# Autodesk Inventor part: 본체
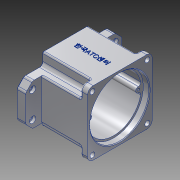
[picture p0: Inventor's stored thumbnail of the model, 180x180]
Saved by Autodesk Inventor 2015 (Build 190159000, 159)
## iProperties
Created: 2016-02
Part Number: 본체
Material: Aluminum 6061
Document SubType Name: Modeling
Designer: Administrator
Density: 2.7 g/cm^3
Appearance: Aluminum - Flat
Mass: 873.805 g
Surface Area: 764.086 cm^2
Volume: 323.632 cm^3
Author: Administrator
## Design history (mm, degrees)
sketch "Sketch1"
  geometry: L1 (60, 30)-(-60, 30); L2 (-70, 20)-(-70, -20); L3 (-60, -30)-(60, -30); L4 (70, -20)-(70, 20); L5 (70, 30)-(-70, -30); L6 (-70, 30)-(70, -30); L7 (60, 30)-(70, 20); L8 (60, -30)-(70, -20); L9 (-60, 30)-(-70, 20); L10 (-60, -30)-(-70, -20); 1 further point
  constraints: 20 end point, 8 point on line, 2 midpoint, 2 parallel, 1 horizontal, 1 perpendicular
  dimensions: "d0" = 140 distance of L6.end L5.end; "d1" = 60 distance of L5.end L6.start; "d2" = 10 distance of L1.start L5.start; "d3" = 10 distance of L4.end L5.start (= d2); "d4" = 10 distance of L3.end L6.end (= d2); "d5" = 10 distance of L4.start L6.end (= d4); "d6" = 10 distance of L1.end L6.start (= d2); "d7" = 10 distance of L2.start L6.start (= d6); "d8" = 10 distance of L3.start L5.end (= d2); "d9" = 10 distance of L2.end L5.end (= d8)
extrude "Extrusion1" new body sketch "Sketch1" distance "d10" = 13; taper "d11" = 0 deg
sketch "Sketch2"
  geometry: L1 (-19, -60)-(19, -60); L2 (19, -60)-(19, 60); L3 (19, 60)-(-19, 60); L4 (-19, 60)-(-19, -60); L5 (-19, -60)-(19, 60); L6 (19, -60)-(-19, 60); 5 further points
  constraints: 12 end point, 4 coincident, 2 midpoint, 2 parallel, 1 horizontal, 1 perpendicular
  dimensions: "d12" = 38 distance of L3.end L2.end; "d13" = 120 distance of L2.end L1.end
hole "Hole1" sketch "Sketch2" at (-19, -60), (19, -60), (19, 60), (-19, 60) diameter "d14" = 5; stored, may be unused: countersink angle "d18" = 90 deg, drill point angle "d20" = 0 deg; dims "d15" = 6.35, "d16" = 9, "d17" = 4, "d19" = 13
sketch "Sketch3"
  geometry: L1 (-47, -47)-(47, -47); L2 (47, -47)-(47, 47); L3 (47, 47)-(-47, 47); L4 (-47, 47)-(-47, -47); L5 (-47, -47)-(47, 47); L6 (47, -47)-(-47, 47); 1 further point
  constraints: 12 end point, 2 midpoint, 2 parallel, 1 horizontal, 1 perpendicular
  dimensions: "d21" = 94 distance of L3.end L2.end; "d22" = 94 distance of L2.end L1.end
extrude "Extrusion2" join sketch "Sketch3" distance "d23" = 67; taper "d24" = 0 deg
sketch "Sketch4"
  geometry: L1 (30, 33)-(47, 33); L2 (47, 33)-(47, 47); L3 (47, 47)-(30, 47); L4 (30, 47)-(30, 33); L5 (30, 33)-(47, 47); L6 (47, 33)-(30, 47); L7 (47, 47)-(47, -47) reference; L8 (30, 47)-(47, 47) reference; 2 further points
  constraints: 12 end point, 2 midpoint, 2 parallel, 1 collinear, 1 horizontal, 1 perpendicular
  dimensions: "d25" = 33 vertical distance of point (0, 0) L1.end; "d26" = 30 distance from line of L4 point (0, 0)
extrude "Extrusion3" cut sketch "Sketch4" distance "d27" = 57; taper "d28" = 0 deg
mirror "Mirror1"
mirror "Mirror2"
sketch "Sketch5"
  geometry: L1 (40, 40)-(-40, 40); L2 (-40, 40)-(-40, -40); L3 (-40, -40)-(40, -40); L4 (40, -40)-(40, 40); L5 (40, 40)-(-40, -40); L6 (-40, 40)-(40, -40); C1 r 3.5 at (-40, -40); C2 r 3.5 at (-40, 40); C3 r 3.5 at (40, 40); C4 r 3.5 at (40, -40); 1 further point
  constraints: 12 end point, 4 centre point, 4 coincident, 2 midpoint, 2 parallel, 1 horizontal, 1 perpendicular
  dimensions: "d29" = 80 distance of L3.end L2.end; "d30" = 80 distance of L2.end L1.end; "d31" = 7 diameter of C1; "d32" = 7 diameter of C2; "d33" = 7 diameter of C3; "d34" = 7 diameter of C4
extrude "Extrusion4" cut sketch "Sketch5" distance "d35" = 10; taper "d36" = 0 deg
sketch "Sketch6"
  geometry: L1 (30, -33)-(47, -33) reference; L2 (47, 33)-(47, -33) reference; L3 (47, 33)-(30, 33) reference; L4 (30, 33)-(30, -33) reference; L5 (-47, -33)-(-30, -33) reference; L6 (-30, -33)-(-30, 33) reference; L7 (-30, 33)-(-47, 33) reference; L8 (-47, -33)-(-47, 33) reference; 1 further point
extrude "Extrusion5" join sketch "Sketch6" distance "d37" = 13; taper "d38" = 0 deg
sketch "Sketch7"
  geometry: C1 r 28 at (11, 0); 1 further point
  constraints: 1 centre point, 1 horizontal alignment
  dimensions: "d39" = 56 diameter of C1; "d40" = 11 distance of point (0, 0) C1.centre
extrude "Extrusion6" join sketch "Sketch7" distance "d41" = 7; taper "d42" = -10 deg
sketch "Sketch8"
  geometry: 2 further points
  constraints: 1 coincident
hole "Hole2" sketch "Sketch8" at (0, 0) diameter "d43" = 80; stored, may be unused: countersink angle "d47" = 90 deg, drill point angle "d49" = 0 deg; dims "d44" = 6.35, "d45" = 86, "d46" = 9, "d48" = 71
sketch "Sketch9"
  geometry: A1 r 21 centre (-11, 0) between (7.984, 8.978) and (7.984, -8.978); A2 r 15 centre (20, 0) between (7.984, -8.978) and (7.984, 8.978); 1 further point
  constraints: 4 point on circle, 2 centre point, 2 horizontal alignment
  dimensions: "d50" = 21 radius of A1; "d51" = 15 radius of A2; "d52" = 11 distance of point (0, 0) A1.centre; "d53" = 20 distance of point (0, 0) A2.centre
extrude "Extrusion7" join sketch "Sketch9" distance "d54" = 7; taper "d55" = 0 deg
hole "Hole3" diameter "d58" = 25; stored, may be unused: countersink angle "d62" = 90 deg, drill point angle "d64" = 0 deg; dims "d59" = 6.35, "d60" = 35, "d61" = 10, "d63" = 15, "d93" = 10, "d94" = 10
hole "Hole4" diameter "d67" = 19; stored, may be unused: countersink angle "d71" = 90 deg, drill point angle "d73" = 0 deg; dims "d65" = 10, "d66" = 10, "d68" = 6.35, "d69" = 22, "d70" = 7, "d72" = 8
hole "Hole5" diameter "d76" = 32; stored, may be unused: countersink angle "d80" = 90 deg, drill point angle "d82" = 0 deg; dims "d77" = 6.35, "d78" = 22, "d79" = 7, "d81" = 8, "d95" = 10, "d96" = 10
chamfer "Chamfer1" distance "d83" = 1; stored, may be unused: second distance "d84" = 2, angle "d85" = 45 deg
fillet "Fillet2" dims "d87" = 2
sketch "Sketch12" dims "d98" = 36
  geometry: A1 r 40 centre (0, 0) between (-8.214, -39.148) and (8.214, -39.148) reference; A2 r 4 centre (0, -36) between (3.997, -35.852) and (-3.997, -35.852); A3 r 3.5 centre (-7.495, -35.722) between (-8.214, -39.148) and (-3.997, -35.852); A4 r 3.5 centre (7.495, -35.722) between (3.997, -35.852) and (8.214, -39.148); A5 r 40 centre (0, 0) between (-8.214, -39.148) and (8.214, -39.148); 2 further points
  constraints: 10 point on circle, 4 centre point, 4 tangent, 2 coincident, 2 vertical alignment, 1 equal radius, 2 other
  dimensions: "d97" = 4 radius of A2; "d99" = 3.5 radius of A3; "d100" = 3.5 radius of A4 (derived)
extrude "Extrusion8" join sketch "Sketch12" distance "d101" = 62; taper "d102" = 0 deg
mirror "Mirror3"
sketch "Sketch13"
  geometry: A1 r 4 centre (0, -36) between (3.997, -35.852) and (-3.997, -35.852) reference; A2 r 4 centre (0, 36) between (-3.997, 35.852) and (3.997, 35.852) reference; 3 further points
  constraints: 2 coincident
hole "Hole6" sketch "Sketch13" at (0, -36), (0, 36) diameter "d103" = 3.242; stored, may be unused: countersink angle "d107" = 90 deg, drill point angle "d109" = 118 deg; dims "d104" = 7, "d105" = 22, "d106" = 7, "d108" = 9
fillet "Fillet3" dims "d110" = 5
fillet "Fillet4" dims "d111" = 8
fillet "Fillet5" dims "d112" = 2
sketch "Sketch14"
  geometry: L1 (-80, 8)-(-80, 70) reference; L2 (0, 78)-(0, 0) reference; 3 further points
  constraints: 1 horizontal alignment, 1 midpoint, 1 other
  dimensions: "d113" = 40 distance from line of L2 point (-40, 39)
emboss "Emboss1" sketch "Sketch14" dims "d0" = 140, "d1" = 60, "d2" = 10, "d3" = 10 (= d2), "d4" = 10 (= d2), "d5" = 10 (= d4), "d6" = 10 (= d2), "d7" = 10 (= d6), "d8" = 10 (= d2), "d9" = 10 (= d8), "d114" = 0.5, "d115" = 0
sketch "Sketch17"
  geometry: L1 (30, 38)-(30, 57.929) reference; L2 (28.536, 61.464)-(21.464, 68.536) reference; L3 (17.929, 70)-(-17.929, 70) reference; L4 (-21.464, 68.536)-(-28.536, 61.464) reference; L5 (-30, 57.929)-(-30, 38) reference; L6 (-35, 33)-(-45, 33) reference; L7 (-47, 31)-(-47, -31) reference; L8 (-45, -33)-(-35, -33) reference; L9 (-30, -38)-(-30, -57.929) reference; L10 (-28.536, -61.464)-(-21.464, -68.536) reference; L11 (-17.929, -70)-(17.929, -70) reference; L12 (21.464, -68.536)-(28.536, -61.464) reference; L13 (30, -57.929)-(30, -38) reference; L14 (35, -33)-(45, -33) reference; L15 (47, -31)-(47, 31) reference; L16 (45, 33)-(35, 33) reference; L17 (46, 31)-(46, -31); L18 (45, -32)-(35, -32); L19 (29, -38)-(29, -57.929); L20 (27.828, -60.757)-(20.757, -67.828); L21 (17.929, -69)-(-17.929, -69); L22 (-20.757, -67.828)-(-27.828, -60.757); L23 (-29, -57.929)-(-29, -38); L24 (-35, -32)-(-45, -32); L25 (-46, -31)-(-46, 31); L26 (-45, 32)-(-35, 32); L27 (-29, 38)-(-29, 57.929); L28 (-27.828, 60.757)-(-20.757, 67.828); L29 (-17.929, 69)-(17.929, 69); L30 (20.757, 67.828)-(27.828, 60.757); L31 (29, 57.929)-(29, 38); L32 (35, 32)-(45, 32); C1 r 28 at (11, 0) reference; A1 r 5 centre (25, 57.929) between (30, 57.929) and (28.536, 61.464) reference; A2 r 5 centre (17.929, 65) between (21.464, 68.536) and (17.929, 70) reference; A3 r 5 centre (-17.929, 65) between (-17.929, 70) and (-21.464, 68.536) reference; A4 r 5 centre (-25, 57.929) between (-28.536, 61.464) and (-30, 57.929) reference; A5 r 5 centre (-35, 38) between (-35, 33) and (-30, 38) reference; A6 r 2 centre (-45, 31) between (-45, 33) and (-47, 31) reference; A7 r 2 centre (-45, -31) between (-47, -31) and (-45, -33) reference; A8 r 5 centre (-35, -38) between (-30, -38) and (-35, -33) reference; A9 r 5 centre (-25, -57.929) between (-30, -57.929) and (-28.536, -61.464) reference; A10 r 5 centre (-17.929, -65) between (-21.464, -68.536) and (-17.929, -70) reference; A11 r 5 centre (17.929, -65) between (17.929, -70) and (21.464, -68.536) reference; A12 r 5 centre (25, -57.929) between (28.536, -61.464) and (30, -57.929) reference; A13 r 5 centre (35, -38) between (35, -33) and (30, -38) reference; A14 r 2 centre (45, -31) between (45, -33) and (47, -31) reference; A15 r 2 centre (45, 31) between (47, 31) and (45, 33) reference; A16 r 5 centre (35, 38) between (30, 38) and (35, 33) reference; A17 r 1 centre (45, -31) between (45, -32) and (46, -31); A18 r 6 centre (35, -38) between (35, -32) and (29, -38); A19 r 4 centre (25, -57.929) between (27.828, -60.757) and (29, -57.929); A20 r 4 centre (17.929, -65) between (17.929, -69) and (20.757, -67.828); A21 r 4 centre (-17.929, -65) between (-20.757, -67.828) and (-17.929, -69); A22 r 4 centre (-25, -57.929) between (-29, -57.929) and (-27.828, -60.757); A23 r 6 centre (-35, -38) between (-29, -38) and (-35, -32); A24 r 1 centre (-45, -31) between (-46, -31) and (-45, -32); A25 r 1 centre (-45, 31) between (-45, 32) and (-46, 31); A26 r 6 centre (-35, 38) between (-35, 32) and (-29, 38); A27 r 4 centre (-25, 57.929) between (-27.828, 60.757) and (-29, 57.929); A28 r 4 centre (-17.929, 65) between (-17.929, 69) and (-20.757, 67.828); A29 r 4 centre (17.929, 65) between (20.757, 67.828) and (17.929, 69); A30 r 4 centre (25, 57.929) between (29, 57.929) and (27.828, 60.757); A31 r 6 centre (35, 38) between (29, 38) and (35, 32); A32 r 1 centre (45, 31) between (46, 31) and (45, 32); 1 further point
  constraints: 32 end point, 32 point on circle, 16 centre point, 31 other
  dimensions: "d116" = 1 distance between parallel lines of L15 L17
extrude "Extrusion9" cut sketch "Sketch17" distance "d117" = 1; taper "d118" = 0 deg
fillet "Fillet6" dims "d119" = 0.3
fillet "Fillet7" dims "d120" = 3
body "Solid1"
node "Projected Loop1"
node "Projected Loop2"
other parameters: "d91" = 3.5
